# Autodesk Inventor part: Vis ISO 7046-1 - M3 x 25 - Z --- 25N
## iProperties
Created: 2011-01
Part Number: Vis ISO 7046-1 - M3 x 25 - Z --- 25N
Document SubType Name: Modeling
Designer: eric
Density: 1 g/cm^3
Mass: 0.187935 g
Surface Area: 2.94333 cm^2
Volume: 0.187935 cm^3
Author: eric
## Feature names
1. Base1
